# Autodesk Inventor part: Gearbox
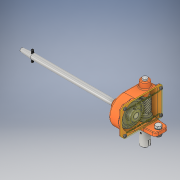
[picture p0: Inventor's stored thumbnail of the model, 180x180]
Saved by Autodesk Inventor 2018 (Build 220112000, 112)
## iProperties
Created: 2018-11
Part Number: Gearbox
Material: Generic
Document SubType Name: Modeling
Designer: mohammad
Density: 1 g/cm^3
Appearance: Default
Author: mohammad
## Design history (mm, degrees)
derived "Gearbox.ipt"
feature "Solid1::Gearbox.ipt"
feature "Solid5::Gearbox.ipt"
feature "Solid6::Gearbox.ipt"
feature "Solid10::Gearbox.ipt"
feature "Solid11::Gearbox.ipt"
feature "Solid12::Gearbox.ipt"
feature "Solid14::Gearbox.ipt"
feature "Solid15::Gearbox.ipt"
feature "Solid16::Gearbox.ipt"
feature "Solid17::Gearbox.ipt"
feature "Solid18::Gearbox.ipt"
feature "Solid19::Gearbox.ipt"
feature "Solid20::Gearbox.ipt"
feature "Solid21::Gearbox.ipt"
feature "Solid22::Gearbox.ipt"
feature "Solid23::Gearbox.ipt"
feature "Solid26::Gearbox.ipt"
feature "Solid27::Gearbox.ipt"
feature "Solid28::Gearbox.ipt"
feature "Solid29::Gearbox.ipt"
feature "Solid30::Gearbox.ipt"
feature "Solid31::Gearbox.ipt"
feature "Solid32::Gearbox.ipt"
feature "Solid42::Gearbox.ipt"
feature "Solid43::Gearbox.ipt"
tag "TaggingFeature1"
body "Solid1"
body "Solid2"
body "Solid3"
body "Solid4"
body "Solid5"
body "Solid6"
body "Solid7"
body "Solid8"
body "Solid9"
body "Solid10"
body "Solid11"
body "Solid12"
body "Solid13"
body "Solid14"
body "Solid15"
body "Solid16"
body "Solid17"
body "Solid18"
body "Solid19"
body "Solid20"
body "Solid21"
body "Solid22"
body "Solid23"
body "Solid24"
body "Solid25"
